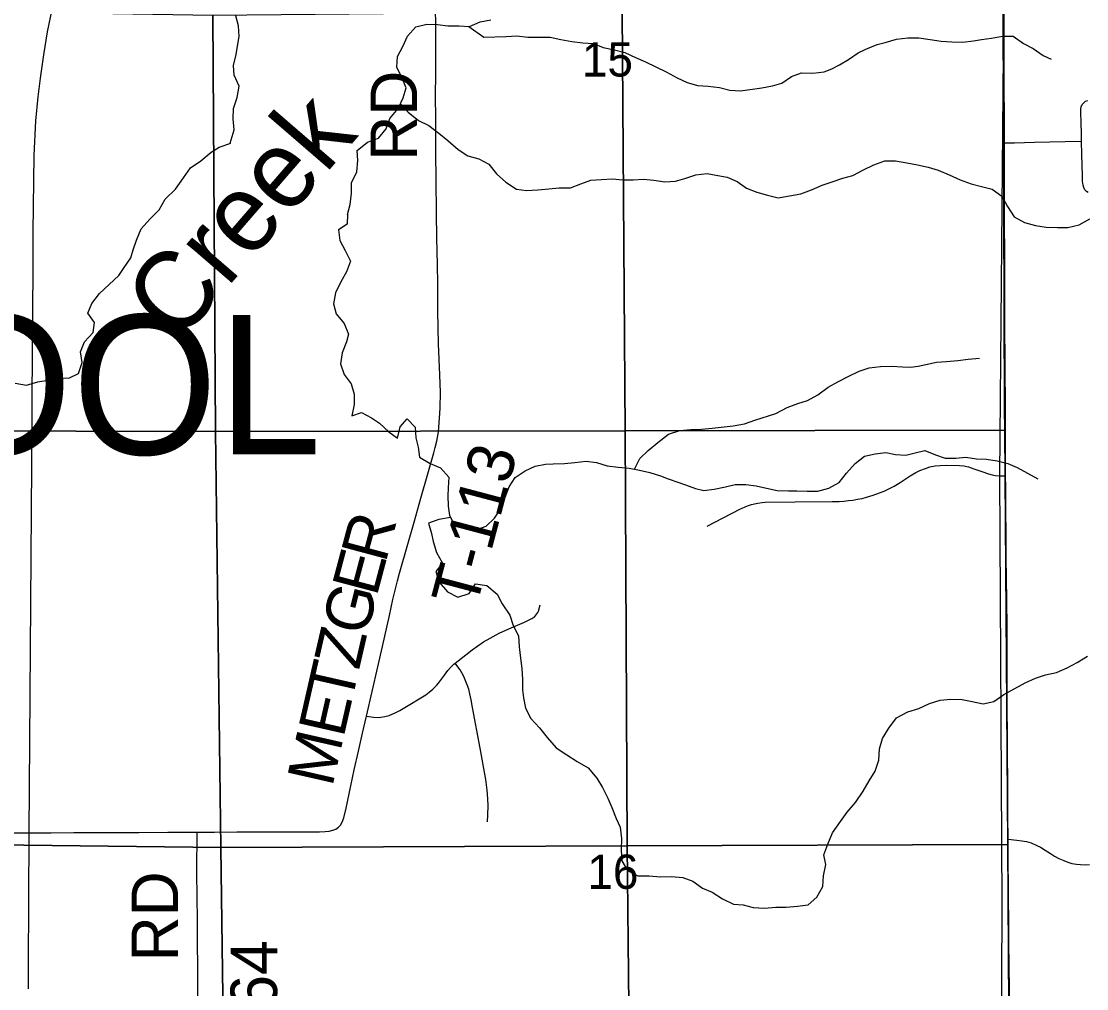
# Model space of a CAD drawing. Extents: x 0 to 34, y 0 to 22.
# Drawn here: x 3.679 to 4.329, y 18.513 to 19.103 of the extents above; entities that cross this region are included whole.
import ezdxf

# ---------------------------------------------------------------- set-up
doc = ezdxf.new("R2010")
doc.units = 0
for name, color, linetype in [('GM_X_County_Road', 7, 'Continuous'), ('GM_X_Minor_River', 7, 'Continuous'), ('GM_X_Minor_River_Text', 7, 'Continuous'), ('GM_X_Rail_Line', 7, 'Continuous'), ('GM_X_Rail_Line_Text', 7, 'Continuous'), ('GM_X_Section', 7, 'Continuous'), ('GM_X_Section_Text', 7, 'Continuous'), ('GM_X_Township', 7, 'Continuous'), ('GM_X_Township_Road', 7, 'Continuous'), ('GM_X_Township_Road_Text', 7, 'Continuous'), ('GM_X_Township_Text', 7, 'Continuous')]:
    doc.layers.add(name, color=color, linetype=linetype)

msp = doc.modelspace()

# ---------------------------------------------------------------- linework, layer by layer
at = {"layer": 'GM_X_County_Road'}
msp.add_lwpolyline([(4.28181, 18.49279), (4.28167, 18.5137), (4.28154, 18.5249), (4.2814, 18.54296), (4.28129, 18.55583), (4.28121, 18.56569), (4.28112, 18.57627), (4.28101, 18.58858), (4.28098, 18.6039), (4.28077, 18.61765), (4.28067, 18.63748), (4.28057, 18.65711), (4.28044, 18.6945), (4.28033, 18.70517), (4.28025, 18.73226), (4.28009, 18.75044), (4.27991, 18.76239), (4.27983, 18.77639), (4.27973, 18.79135), (4.27963, 18.80345), (4.27949, 18.81855), (4.27937, 18.82563), (4.27932, 18.85953), (4.27926, 18.87357), (4.2792, 18.88651), (4.27906, 18.90082), (4.27896, 18.91164), (4.2789, 18.93908), (4.27886, 18.94998), (4.2788, 18.99117), (4.27869, 19.00782), (4.27875, 19.02894), (4.27868, 19.0441), (4.2786, 19.06338), (4.27851, 19.09573), (4.27854, 19.11102)], dxfattribs=at)
at = {"layer": 'GM_X_Minor_River'}
for points in [[(3.80634, 19.02876), (3.80874, 19.03687), (3.8082, 19.04353), (3.80823, 19.05), (3.81055, 19.05664), (3.81172, 19.06349), (3.80871, 19.07035), (3.80836, 19.07625), (3.80992, 19.0829), (3.8109, 19.08917), (3.81187, 19.09392), (3.81133, 19.10039), (3.80984, 19.10649)], [(3.8778, 18.98531), (3.87954, 18.99139), (3.88034, 18.99824), (3.88037, 19.00451), (3.88363, 19.01134), (3.88423, 19.01819), (3.88369, 19.02428), (3.88999, 19.02938), (3.89684, 19.03182), (3.90142, 19.0375), (3.90373, 19.04376), (3.90889, 19.05001), (3.91177, 19.05646), (3.9137, 19.06254), (3.91108, 19.06883), (3.90807, 19.07513), (3.90829, 19.08159), (3.91155, 19.08785), (3.91443, 19.09412), (3.91959, 19.09979), (3.92624, 19.10147), (3.93289, 19.10124), (3.93915, 19.10045), (3.94599, 19.10041), (3.95226, 19.09999), (3.95873, 19.10281), (3.96538, 19.10411)], [(3.95183, 19.09993), (3.96096, 19.09348), (3.97464, 19.09378), (3.9811, 19.09432), (3.98793, 19.09352), (4.0016, 19.09344), (4.00805, 19.09208), (4.0147, 19.0909), (4.02153, 19.0901), (4.02799, 19.08968), (4.03386, 19.08718), (4.04069, 19.08581), (4.04714, 19.08406), (4.05358, 19.08098), (4.05965, 19.07847), (4.0659, 19.0754), (4.07234, 19.07232), (4.07897, 19.06867), (4.08503, 19.06578), (4.09148, 19.06403), (4.09794, 19.06362), (4.10477, 19.06282), (4.11122, 19.06107), (4.11768, 19.06065), (4.1306, 19.06248), (4.13725, 19.06378), (4.14296, 19.06546), (4.14868, 19.06942), (4.15496, 19.07167), (4.16179, 19.07144), (4.16864, 19.07235), (4.17339, 19.07404), (4.17815, 19.07668), (4.18349, 19.07988), (4.18939, 19.08384), (4.19415, 19.0861), (4.201, 19.08892), (4.20595, 19.09022), (4.2128, 19.09228), (4.21964, 19.093), (4.22648, 19.09315), (4.23331, 19.09197), (4.24014, 19.09098), (4.2466, 19.09057), (4.25305, 19.09034), (4.25989, 19.09125), (4.26465, 19.09199), (4.27073, 19.09291), (4.27757, 19.09401), (4.28403, 19.09416), (4.29027, 19.08956), (4.29615, 19.08649), (4.30239, 19.08227), (4.30713, 19.07996)], [(3.91005, 19.05305), (3.91496, 19.0477), (3.9212, 19.04253), (3.92745, 19.03964), (3.93351, 19.03485), (3.93918, 19.03044), (3.94542, 19.02489), (3.95129, 19.02105), (3.95793, 19.0193), (3.96418, 19.01585), (3.96871, 19.01011), (3.97457, 19.00494), (3.98101, 19.00072), (3.98708, 18.99993), (3.99392, 19.00027), (4.00076, 19.0008), (4.00703, 19.00153), (4.01387, 19.00149), (4.02015, 19.00393), (4.02643, 19.00618), (4.03289, 19.00652), (4.03954, 19.00706), (4.04561, 19.00645), (4.05207, 19.00642), (4.05853, 19.00676), (4.06479, 19.00616), (4.07144, 19.00517), (4.0779, 19.00551), (4.08379, 19.00719), (4.09045, 19.00944), (4.09729, 19.01016), (4.10374, 19.00899), (4.10944, 19.008), (4.11569, 19.00531), (4.12137, 19.00128), (4.12762, 18.99877), (4.13407, 18.99702), (4.14071, 18.99547), (4.14755, 18.99657), (4.1544, 18.99786), (4.16106, 19.0003), (4.16753, 19.00312), (4.17362, 19.00518), (4.18009, 19.00742), (4.18617, 19.0091), (4.19265, 19.01249), (4.19893, 19.0155), (4.20578, 19.01793), (4.21224, 19.0179), (4.21907, 19.01672), (4.22571, 19.01554), (4.23216, 19.01417), (4.23823, 19.01224), (4.24505, 19.00935), (4.25168, 19.00646), (4.25832, 19.00395), (4.26477, 19.00239), (4.27122, 19.00064), (4.27708, 18.99642), (4.28047, 18.99013), (4.28462, 18.98383), (4.29087, 18.98037), (4.2977, 18.97843), (4.30415, 18.97744), (4.31098, 18.97721), (4.31744, 18.97737), (4.32429, 18.97885), (4.33076, 18.98262)], [(3.67521, 18.88219), (3.68204, 18.88101), (3.68889, 18.88306), (3.69535, 18.88417), (3.70181, 18.88527), (3.70827, 18.88543), (3.71379, 18.88825), (3.71592, 18.8949), (3.715, 18.90137), (3.7175, 18.90744), (3.72265, 18.91312), (3.72344, 18.91921), (3.71948, 18.92494), (3.72198, 18.93082), (3.72657, 18.93707), (3.7384, 18.94804), (3.74165, 18.95278), (3.74567, 18.95884), (3.74722, 18.96359), (3.74914, 18.96948), (3.75203, 18.9765), (3.75737, 18.98237), (3.76291, 18.98804), (3.76655, 18.99468), (3.77304, 19.00073), (3.77782, 19.00755), (3.78203, 19.01362), (3.78832, 19.01796), (3.79461, 19.02325), (3.79957, 19.02627), (3.80664, 19.02876)], [(3.8778, 18.98532), (3.87777, 18.97942), (3.87244, 18.97583), (3.87317, 18.96936), (3.87655, 18.96325), (3.87975, 18.95677), (3.87725, 18.95032), (3.8738, 18.94406), (3.87054, 18.93742), (3.86936, 18.93077), (3.87104, 18.92467), (3.87595, 18.91874), (3.87858, 18.91226), (3.87723, 18.90751), (3.87453, 18.90068), (3.87355, 18.89403), (3.8758, 18.88755), (3.88014, 18.88182), (3.882, 18.87553), (3.88197, 18.86925), (3.88061, 18.86241), (3.88651, 18.86428), (3.89257, 18.86101), (3.89749, 18.85794), (3.90316, 18.85258), (3.90846, 18.84875), (3.91001, 18.85559), (3.91422, 18.86051), (3.91913, 18.85535), (3.91967, 18.84888), (3.92097, 18.84316), (3.92189, 18.83707), (3.92832, 18.83323), (3.93458, 18.83053), (3.93968, 18.8248), (3.93927, 18.81833), (3.93905, 18.81358), (3.9394, 18.80711), (3.94013, 18.8014), (3.94333, 18.7951), (3.94978, 18.79335), (3.95623, 18.79275), (3.96251, 18.795), (3.96766, 18.79991), (3.97187, 18.80617), (3.97399, 18.81262), (3.97649, 18.81889), (3.98013, 18.82476), (3.98623, 18.82873), (3.99232, 18.83155), (3.9986, 18.83284), (4.00334, 18.83301), (4.01018, 18.83316), (4.01664, 18.83388), (4.02348, 18.83461), (4.02975, 18.83381), (4.03639, 18.83187), (4.04303, 18.83107), (4.04967, 18.83047), (4.05593, 18.8291), (4.06238, 18.82773), (4.06883, 18.8258), (4.07357, 18.82387), (4.07945, 18.82193), (4.08419, 18.82019), (4.09025, 18.81788), (4.09538, 18.81671), (4.10165, 18.81762), (4.10849, 18.81892), (4.11439, 18.82041), (4.12085, 18.82037), (4.1273, 18.81957), (4.13356, 18.81821), (4.14001, 18.81684), (4.14685, 18.81661), (4.15197, 18.81659), (4.15824, 18.81636), (4.16489, 18.81632), (4.17154, 18.81819), (4.17783, 18.82158), (4.18241, 18.82726), (4.18757, 18.83313), (4.19329, 18.83766), (4.19976, 18.83915), (4.20622, 18.83987), (4.21229, 18.8387), (4.21856, 18.83828), (4.22426, 18.83977), (4.23016, 18.84107), (4.2366, 18.83856), (4.24248, 18.83644), (4.24893, 18.8364), (4.25521, 18.83713), (4.26166, 18.83614), (4.26773, 18.83592), (4.27419, 18.83493), (4.28083, 18.83318), (4.28651, 18.83087), (4.29901, 18.82395)], [(4.05295, 18.82975), (4.05616, 18.83633), (4.06131, 18.84125), (4.06722, 18.84597), (4.07371, 18.85107), (4.08056, 18.85331), (4.0874, 18.85404), (4.09385, 18.85419), (4.10031, 18.85473), (4.11324, 18.85618), (4.12008, 18.85747), (4.12636, 18.85972), (4.13929, 18.86383), (4.14615, 18.86741), (4.15262, 18.86985), (4.15852, 18.87172), (4.1648, 18.8751), (4.17109, 18.87983), (4.177, 18.88303), (4.18366, 18.8866), (4.19013, 18.88961), (4.19622, 18.89167), (4.20306, 18.8924), (4.20971, 18.89274), (4.21655, 18.89232), (4.22129, 18.8921), (4.22605, 18.89265), (4.2308, 18.89376), (4.23726, 18.89506), (4.24334, 18.89541), (4.25018, 18.89613), (4.25664, 18.89685), (4.26349, 18.89758)], [(3.94077, 18.80022), (3.93366, 18.79896), (3.92738, 18.79671), (3.92906, 18.79042), (3.93018, 18.78566), (3.93223, 18.7788), (3.93581, 18.77232), (3.93179, 18.7672), (3.93385, 18.76072), (3.93895, 18.7548), (3.9452, 18.75172), (3.95205, 18.75396), (3.95607, 18.75984), (3.9629, 18.75885), (3.96914, 18.75349), (3.97234, 18.74757), (3.97686, 18.7407), (3.97892, 18.73441), (3.98212, 18.72793), (3.98265, 18.72126), (3.98338, 18.71441), (3.9843, 18.70813), (3.98464, 18.70128), (3.98461, 18.695), (3.98535, 18.69024), (3.98646, 18.68396), (3.98965, 18.67747), (3.99494, 18.67193), (3.99966, 18.666), (4.00514, 18.6597), (4.01176, 18.65547), (4.01801, 18.65125), (4.02464, 18.64741), (4.02992, 18.64111), (4.03351, 18.63538), (4.0367, 18.62889), (4.03914, 18.62317), (4.04177, 18.6165), (4.04421, 18.61116), (4.04513, 18.60431), (4.0449, 18.59746), (4.04525, 18.59061), (4.04864, 18.58469), (4.05508, 18.58162), (4.06192, 18.58158), (4.06875, 18.58097), (4.07559, 18.58112), (4.08242, 18.58051), (4.08849, 18.5782), (4.09455, 18.57398), (4.10042, 18.57147), (4.10667, 18.56744), (4.1133, 18.56417), (4.11937, 18.56376), (4.12544, 18.5622), (4.13228, 18.56178), (4.13912, 18.56232), (4.14558, 18.56247), (4.15242, 18.563), (4.15888, 18.56373), (4.16422, 18.56846), (4.16786, 18.57509), (4.16827, 18.58156), (4.16964, 18.5884), (4.16853, 18.5943), (4.17084, 18.60095), (4.17372, 18.60778), (4.17869, 18.6146), (4.18271, 18.62048), (4.18787, 18.62635), (4.19246, 18.63317), (4.1961, 18.63943), (4.19974, 18.64549), (4.20205, 18.65214), (4.20247, 18.65898), (4.20421, 18.66544), (4.20823, 18.6717), (4.21282, 18.67795), (4.21967, 18.68172), (4.22652, 18.68377), (4.23299, 18.68678), (4.23946, 18.68884), (4.24592, 18.68937), (4.25295, 18.68914), (4.25902, 18.68797), (4.26566, 18.6866), (4.27231, 18.68789), (4.27841, 18.69223), (4.29136, 18.69939), (4.29765, 18.70221), (4.30373, 18.70427), (4.31039, 18.70556), (4.31686, 18.70857), (4.32314, 18.71177), (4.32943, 18.71554)]]:
    msp.add_lwpolyline(points, dxfattribs=at)
at = {"layer": 'GM_X_Rail_Line'}
msp.add_lwpolyline([(3.68321, 18.51252), (3.68335, 18.52615), (3.68363, 18.60767), (3.68539, 18.8321), (3.68546, 18.87311), (3.68595, 18.92557), (3.68616, 18.95267), (3.68616, 18.97444), (3.68667, 19.02131), (3.6878, 19.04242), (3.68925, 19.05702), (3.69052, 19.0684), (3.69255, 19.08272), (3.69485, 19.09663), (3.69943, 19.11938), (3.70316, 19.13778), (3.71011, 19.17401), (3.73756, 19.31305), (3.74992, 19.37604), (3.77857, 19.5207), (3.78644, 19.55974)], dxfattribs=at)
at = {"layer": 'GM_X_Rail_Line_Text'}
msp.add_lwpolyline([(2.77875, 17.80661), (3.04126, 17.80913), (3.53178, 17.8199), (4.04512, 17.83208), (4.17864, 17.83524), (4.28678, 17.83811), (4.28692, 17.84212), (4.28581, 17.95524), (4.28464, 18.15407), (4.27642, 18.36992), (4.27726, 18.56476), (4.27587, 18.8261), (4.27859, 19.13014), (4.27679, 19.3807), (4.2769, 19.4129), (4.27672, 19.50175), (4.27627, 19.60888)], dxfattribs=at)
at = {"layer": 'GM_X_Section'}
for points in [[(3.79582, 19.10682), (3.79726, 18.85283), (3.54138, 18.85346), (3.53903, 19.11114)], [(4.2777, 19.10976), (4.27852, 18.86654), (4.27864, 18.85366), (4.04732, 18.85326), (4.04538, 19.10932)], [(4.04538, 19.10932), (4.04732, 18.85326), (3.79726, 18.85283), (3.79582, 19.10682)], [(3.79726, 18.85283), (3.80064, 18.5989), (3.54284, 18.60193), (3.54138, 18.85346)], [(4.04732, 18.85326), (4.04842, 18.59978), (3.80064, 18.5989), (3.79726, 18.85283)], [(4.27864, 18.85366), (4.28047, 18.60061), (4.04842, 18.59978), (4.04732, 18.85326)], [(3.80064, 18.5989), (3.80425, 18.32752), (3.54412, 18.32749), (3.54284, 18.60193)], [(4.04842, 18.59978), (4.0513, 18.32631), (3.80425, 18.32752), (3.80064, 18.5989)], [(4.28047, 18.60061), (4.2819, 18.36989), (4.28218, 18.32518), (4.0513, 18.32631), (4.04842, 18.59978)]]:
    msp.add_lwpolyline(points, close=True, dxfattribs=at)
at = {"layer": 'GM_X_Township'}
msp.add_lwpolyline([(5.23962, 17.86489), (4.75674, 17.85444), (4.28987, 17.8422), (4.28692, 17.84212), (4.28581, 17.95524), (4.28464, 18.15407), (4.27642, 18.36992), (4.27726, 18.56476), (4.27587, 18.8261), (4.27859, 19.13014), (4.27679, 19.3807), (4.2769, 19.4129), (4.27672, 19.50175), (4.27627, 19.60888)], dxfattribs=at)
at = {"layer": 'GM_X_Township_Road'}
for points in [[(3.9314, 18.843), (3.9323, 18.84684), (3.93336, 18.85255), (3.9343, 18.86377), (3.9345, 18.86716), (3.93457, 18.87654), (3.93423, 18.88725), (3.9335, 18.90634), (3.93306, 18.92615), (3.93291, 18.94312), (3.9327, 18.95457), (3.93239, 18.97104), (3.93211, 18.98582), (3.93193, 19.00651), (3.93178, 19.02262), (3.93169, 19.04339), (3.93162, 19.05781), (3.93168, 19.07115), (3.93174, 19.08719), (3.93178, 19.09897), (3.93164, 19.11273), (3.93154, 19.12288)], [(4.32981, 18.99862), (4.32871, 18.99933), (4.3277, 19.00034), (4.32704, 19.00161), (4.32664, 19.0031), (4.32634, 19.00561), (4.32629, 19.00895), (4.32597, 19.02175), (4.32576, 19.03), (4.32562, 19.03439), (4.32541, 19.04111), (4.32519, 19.04771), (4.32524, 19.04946), (4.32546, 19.05104), (4.32616, 19.05241), (4.32722, 19.05359), (4.32809, 19.05434), (4.32963, 19.05482)], [(4.27875, 19.02894), (4.28486, 19.02903), (4.29693, 19.02936), (4.30631, 19.02955), (4.31583, 19.02975), (4.32576, 19.03)], [(3.87083, 18.61003), (3.87245, 18.61129), (3.87352, 18.6124), (3.87467, 18.61431), (3.87559, 18.61698), (3.87704, 18.62291), (3.87988, 18.63641), (3.882, 18.64628), (3.88461, 18.65766), (3.88707, 18.66865), (3.88939, 18.67896), (3.89638, 18.70912), (3.89921, 18.72161), (3.90346, 18.74039), (3.90563, 18.75014), (3.90833, 18.76155), (3.90956, 18.76628), (3.91465, 18.78395), (3.91851, 18.79735), (3.92271, 18.81202), (3.92695, 18.82685), (3.93061, 18.83964), (3.9314, 18.843)], [(4.09738, 18.79497), (4.107, 18.79997), (4.11758, 18.80547), (4.11876, 18.80606), (4.12058, 18.80686), (4.12244, 18.80757), (4.12433, 18.80818), (4.12625, 18.80869), (4.1282, 18.80909), (4.13082, 18.80948), (4.13279, 18.80964), (4.15093, 18.80981), (4.17362, 18.81002), (4.17785, 18.8101), (4.18067, 18.81027), (4.18347, 18.81054), (4.18626, 18.81091), (4.18904, 18.81138), (4.19179, 18.81196), (4.19452, 18.81263), (4.19857, 18.81382), (4.20255, 18.81524), (4.20526, 18.81626), (4.20773, 18.81747), (4.2115, 18.8194), (4.21516, 18.82154), (4.22123, 18.82566), (4.22466, 18.8277), (4.22705, 18.82887), (4.23055, 18.83025), (4.23318, 18.83111), (4.23641, 18.8318), (4.23943, 18.8321), (4.24348, 18.83227), (4.25132, 18.8321), (4.25382, 18.83176), (4.25671, 18.83111), (4.26007, 18.82999), (4.26498, 18.82826), (4.26905, 18.82689), (4.27122, 18.82633), (4.27317, 18.82597), (4.27571, 18.82577), (4.27937, 18.82563)], [(3.98583, 18.73634), (3.98628, 18.73653), (3.99035, 18.73852), (3.99211, 18.7399), (3.99346, 18.74142), (3.99392, 18.74222), (3.99431, 18.74318), (3.99538, 18.747)], [(3.88939, 18.67896), (3.89366, 18.6784), (3.89706, 18.67827), (3.9006, 18.67876), (3.90324, 18.67945), (3.90746, 18.68126), (3.90982, 18.6824), (3.91495, 18.68544), (3.92362, 18.6908), (3.92562, 18.69202), (3.92775, 18.69366), (3.92998, 18.69556), (3.93229, 18.69792), (3.93402, 18.70001), (3.93706, 18.7041), (3.93906, 18.70684), (3.94067, 18.7088), (3.94274, 18.71077), (3.94361, 18.71138), (3.95014, 18.71646), (3.95399, 18.71956), (3.95733, 18.72201), (3.9609, 18.72433), (3.96489, 18.72664), (3.97037, 18.72964), (3.97625, 18.73236), (3.98583, 18.73634)], [(3.9633, 18.61459), (3.9636, 18.61871), (3.96366, 18.62416), (3.96358, 18.6286), (3.96315, 18.63388), (3.96223, 18.64041), (3.95876, 18.65936), (3.95413, 18.68424), (3.95324, 18.68904), (3.95259, 18.69264), (3.95182, 18.6954), (3.95095, 18.69817), (3.94973, 18.70117), (3.94878, 18.70317), (3.94764, 18.70548), (3.94655, 18.70725), (3.94523, 18.70903), (3.94361, 18.71138)], [(3.78609, 18.60822), (3.79676, 18.60827), (3.81033, 18.60832), (3.8268, 18.60839), (3.84315, 18.60846), (3.8532, 18.60839), (3.86085, 18.60845), (3.86427, 18.60863), (3.86677, 18.60882), (3.86887, 18.60931), (3.87083, 18.61003)], [(3.67006, 18.6077), (3.68326, 18.60775), (3.69702, 18.60782), (3.71102, 18.60788), (3.72478, 18.60794), (3.73835, 18.60801), (3.7505, 18.60806), (3.76832, 18.60814), (3.78609, 18.60822)], [(3.78662, 18.50249), (3.7865, 18.52612), (3.78643, 18.54018), (3.78636, 18.55523), (3.78622, 18.56788), (3.78604, 18.58422), (3.78609, 18.60822)], [(4.28098, 18.6039), (4.28626, 18.60334), (4.28937, 18.6029), (4.29204, 18.6024), (4.29492, 18.60162), (4.29848, 18.60007), (4.30064, 18.59896), (4.30359, 18.59712), (4.30675, 18.59507), (4.30928, 18.59356), (4.31186, 18.59207), (4.31492, 18.59079), (4.31731, 18.58987), (4.31975, 18.58913), (4.32264, 18.58857), (4.32513, 18.58835), (4.32808, 18.58829), (4.33058, 18.58841)]]:
    msp.add_lwpolyline(points, dxfattribs=at)

# ---------------------------------------------------------------- texts
at = {"layer": 'GM_X_Minor_River_Text'}
msp.add_text('Creek', height=0.047375, rotation=49.17281, dxfattribs=at).set_placement((3.77446, 18.90553))
at = {"layer": 'GM_X_Section_Text'}
for s, p in [('15', (4.02091, 19.06946)), ('16', (4.02424, 18.57357))]:
    msp.add_text(s, height=0.020928, rotation=0.00001, dxfattribs=at).set_placement(p)
at = {"layer": 'GM_X_Township_Road_Text'}
for s, height, rotation, p in [('RD', 0.028409, 90, (3.92036, 19.01812)), ('T-113', 0.028409, 75.16093, (3.95628, 18.74422)), ('R', 0.02841, 74.98963, (3.90105, 18.77191)), ('E', 0.02841, 75.10722, (3.8956, 18.75139)), ('G', 0.02841, 75.9929, (3.88957, 18.72725)), ('Z', 0.02841, 76.99799, (3.88482, 18.70667)), ('T', 0.02841, 77.17574, (3.88011, 18.68597)), ('E', 0.02841, 77.17323, (3.87539, 18.66525)), ('M', 0.02841, 77.17517, (3.86855, 18.63519)), ('RD', 0.028409, 90, (3.77452, 18.52937)), ('T-164', 0.028409, 89.71929, (3.83459, 18.44288))]:
    msp.add_text(s, height=height, rotation=rotation, dxfattribs=at).set_placement(p)
at = {"layer": 'GM_X_Township_Text'}
msp.add_text('LIVERPOOL', height=0.085227, rotation=0.00001, dxfattribs=at).set_placement((3.21593, 18.83873))

doc.saveas('drawing.dxf')
